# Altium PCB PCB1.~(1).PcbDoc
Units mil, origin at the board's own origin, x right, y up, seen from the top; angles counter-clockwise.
Board outline 6000 x 4000 mil, 2 copper layers (Top Layer, Bottom Layer); 4 components, 34 nets, 45 pads, 12 vias.
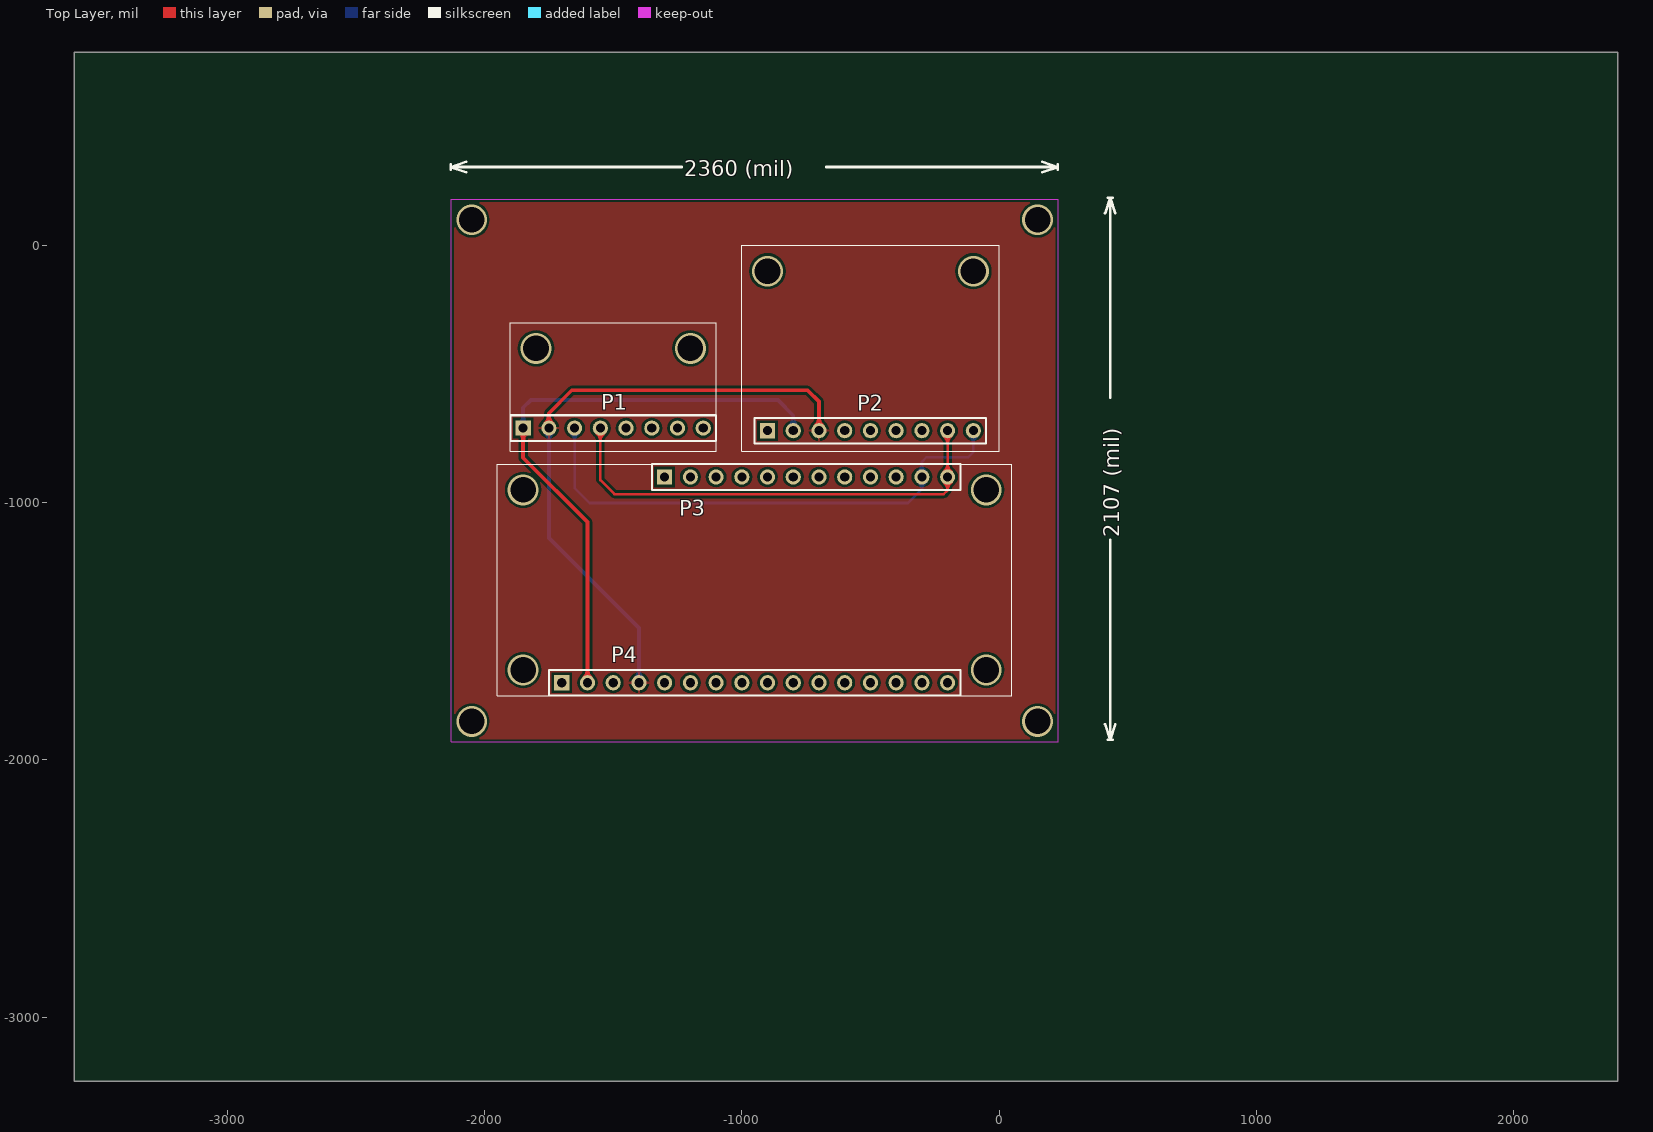
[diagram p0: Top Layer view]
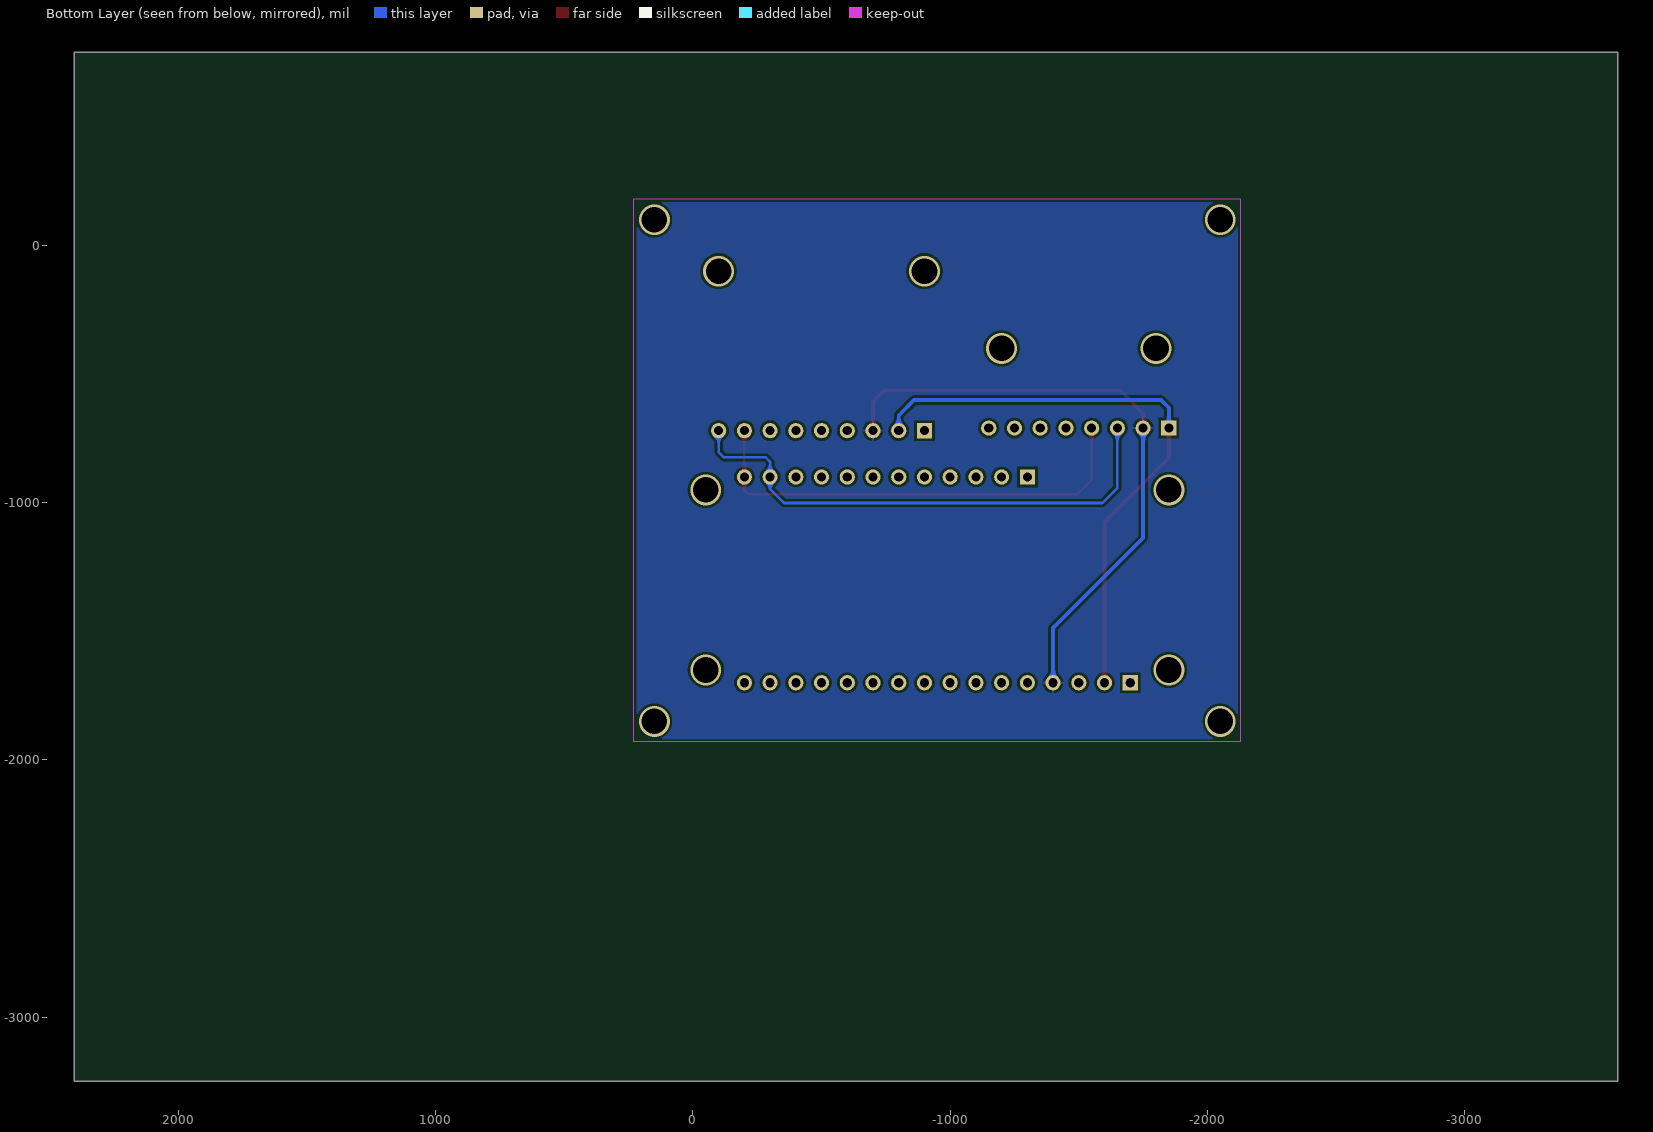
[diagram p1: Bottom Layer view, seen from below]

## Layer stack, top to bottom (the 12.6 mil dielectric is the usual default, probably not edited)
Top Solder: solder mask 0.4, Solder Resist, Dk 3.5
Top Layer: signal copper 1.4
Dielectric 1: dielectric 12.6, FR-4, Dk 4.8
Bottom Layer: signal copper 1.4
Bottom Solder: solder mask 0.4, Solder Resist, Dk 3.5

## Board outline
-3595,-3249 2405,-3249 2405,751 -3595,751

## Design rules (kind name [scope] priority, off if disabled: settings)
Clearance [All] p1: gap=10
PolygonConnect [All] p1: connectstyle=Relief reliefconductorwidth=10 reliefentries=4 polygonreliefangle="90 Angle" airgapwidth=10
RoutingVias [All] p1: holewidth=28 width=50 viastyle="Through Hole" minholewidth=28 minwidth=50 maxholewidth=28 maxwidth=50
SolderMaskExpansion [All] p1: expansion=4
Width [All] p1: maxlimit=20 minlimit=10 preferedwidth=10
30 further rules are at their usual default settings.

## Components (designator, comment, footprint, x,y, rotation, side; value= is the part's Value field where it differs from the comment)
P1 "Header 8" HDR1X8 -1850,-710 r0 top
P2 "Header 9" HDR1X9 -900,-720 r0 top
P3 "Header 12" HDR1X12 -1300,-900 r0 top
P4 "Header 16" HDR1X16 -1700,-1700 r0 top

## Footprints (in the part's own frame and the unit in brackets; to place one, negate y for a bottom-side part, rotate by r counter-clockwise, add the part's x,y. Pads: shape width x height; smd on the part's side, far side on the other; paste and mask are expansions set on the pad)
HDR1X8 [mm] "Connector; Header; 8 Position"
  rect 1.5x1.5 hole 0.9: 1(0,0)
  round 1.5 hole 0.9: 2(2.54,0) 3(5.08,0) 4(7.62,0) 5(10.16,0) 6(12.7,0) 7(15.24,0) 8(17.78,0)
  silkscreen extent -1.27,-1.27 19.05,1.27
HDR1X9 [mm] "Connector; Header; 9 Position"
  rect 1.5x1.5 hole 0.9: 1(0,0)
  round 1.5 hole 0.9: 2(2.54,0) 3(5.08,0) 4(7.62,0) 5(10.16,0) 6(12.7,0) 7(15.24,0) 8(17.78,0) 9(20.32,0)
  silkscreen extent -1.27,-1.27 21.59,1.27
HDR1X12 [mm] "Connector; Header; 12 Position"
  rect 1.5x1.5 hole 0.9: 1(0,0)
  round 1.5 hole 0.9: 2(2.54,0) 3(5.08,0) 4(7.62,0) 5(10.16,0) 6(12.7,0) 7(15.24,0) 8(17.78,0) 9(20.32,0) 10(22.86,0) 11(25.4,0) 12(27.94,0)
  silkscreen extent -1.27,-1.27 29.21,1.27
HDR1X16 [mm] "Connector; Header; 16 Position"
  rect 1.5x1.5 hole 0.9: 1(0,0)
  round 1.5 hole 0.9: 2(2.54,0) 3(5.08,0) 4(7.62,0) 5(10.16,0) 6(12.7,0) 7(15.24,0) 8(17.78,0) 9(20.32,0) 10(22.86,0) 11(25.4,0) 12(27.94,0) 13(30.48,0) 14(33.02,0) 15(35.56,0) 16(38.1,0)
  silkscreen extent -1.27,-1.27 39.37,1.27

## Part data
P1: "Header, 8-Pin"
P2: "Header, 9-Pin"
P3: "Header, 12-Pin"
P4: "Header, 16-Pin"

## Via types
v1: diameter 120, hole 100, Top Layer to Bottom Layer, 12 vias

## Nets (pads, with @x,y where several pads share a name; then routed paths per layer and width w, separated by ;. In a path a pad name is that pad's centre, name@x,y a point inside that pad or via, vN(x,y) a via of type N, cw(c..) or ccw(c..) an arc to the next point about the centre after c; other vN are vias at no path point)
3V3: P1.1 P2.2 P4.2 | length 2318.8
  Top Layer w15: P1.1 -1850,-825 -1600,-1075 P4.2
  Bottom Layer w15: P1.1 -1850,-631 -1820,-601 -860,-601 -800,-661 P2.2
6: P3.9
9~: P3.8
11: P3.6
12: P3.5
13: P3.4
A0: P4.5
A1: P4.6
A2: P4.7
A3: P4.8
A4-: P4.9
A5-: P4.10
ALERT: P1.5
ARF: P4.3
BAT: P3.1
CS: P2.4
DFU: P4.16
EN: P3.2
GND: P1.2 P2.3 P4.4 | length 2411.1
  Top Layer w15: P1.2 -1750,-652 -1661,-563 -744,-563 -700,-607 P2.3
  Bottom Layer w15: P1.2 -1750,-1137 -1400,-1487 P4.4
INT1: P2.5
INT2: P2.6
MISO: P4.13
MOSI: P4.12
RST: P4.1
RX: P4.14
SCK: P4.11
SCL: P1.3 P2.9 P3.11 | length 2034.1
  Bottom Layer w10: P1.3 -1650,-943 -1592,-1001 -354,-1001 -300,-947 P3.11 -300,-841 -283,-824 -121,-824 -100,-803 P2.9
SDA: P1.4 P2.8 P3.12 | length 1813
  Top Layer w10: P1.4 -1550,-912 -1495,-967 -215,-967 -200,-952 P3.12 P2.8
SDO: P2.7
TX: P4.15
USB: P3.3
VIN: P2.1
~5: P3.10
~10: P3.7
pads on no net: P1.6 P1.7 P1.8
copper on no net:
  other v1: -2050,-1850 150,-1850 -1850,-1650 -50,-1650 -1850,-950 -50,-950 -1800,-400 -1200,-400 -900,-100 -100,-100 -2050,100 150,100

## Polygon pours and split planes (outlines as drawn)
GND on Top Layer "Top Layer-No Net" (solid, remove dead copper): -2130,180 -2130,-1930 230,-1930 230,180
GND on Bottom Layer "Top Layer-No Net" (solid, remove dead copper, pour order 3): -2130,180 -2130,-1930 230,-1930 230,180

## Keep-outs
Keep-Out Layer:
  lines w2: -2130,-1930 -2130,180 230,180 230,-1930 -2130,-1930

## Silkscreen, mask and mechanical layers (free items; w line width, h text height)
Top Overlay:
  lines w2: -1950,-1750 -1950,-850 50,-850 50,-1750 -1950,-1750 ; -1900,-800 -1900,-300 -1100,-300 -1100,-800 -1900,-800 ; -1000,-800 -1000,0 0,0 0,-800 -1000,-800
  lines w10: -2132.09,295 -2132.09,315 ; -2072.09,285 -2132.09,305 ; -2072.09,325 -2132.09,305 ; -1233,305 -2132.09,305 ; -671.17,305 227.91,305 ; 167.91,285 227.91,305 ; 167.91,325 227.91,305 ; 227.91,295 227.91,315 ; 412,-1861.58 432,-1921.58 ; 412,125.42 432,185.42 ; 422,-1921.58 442,-1921.58 ; 422,185.42 442,185.42 ; 432,-1144 432,-1921.58 ; 432,-592.17 432,185.42 ; 452,-1861.58 432,-1921.58 ; 452,125.42 432,185.42
  text "2360 (mil)" at -1223,269.01 h60
  text "2107 (mil)" at 467.99,-1134 h60 r90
